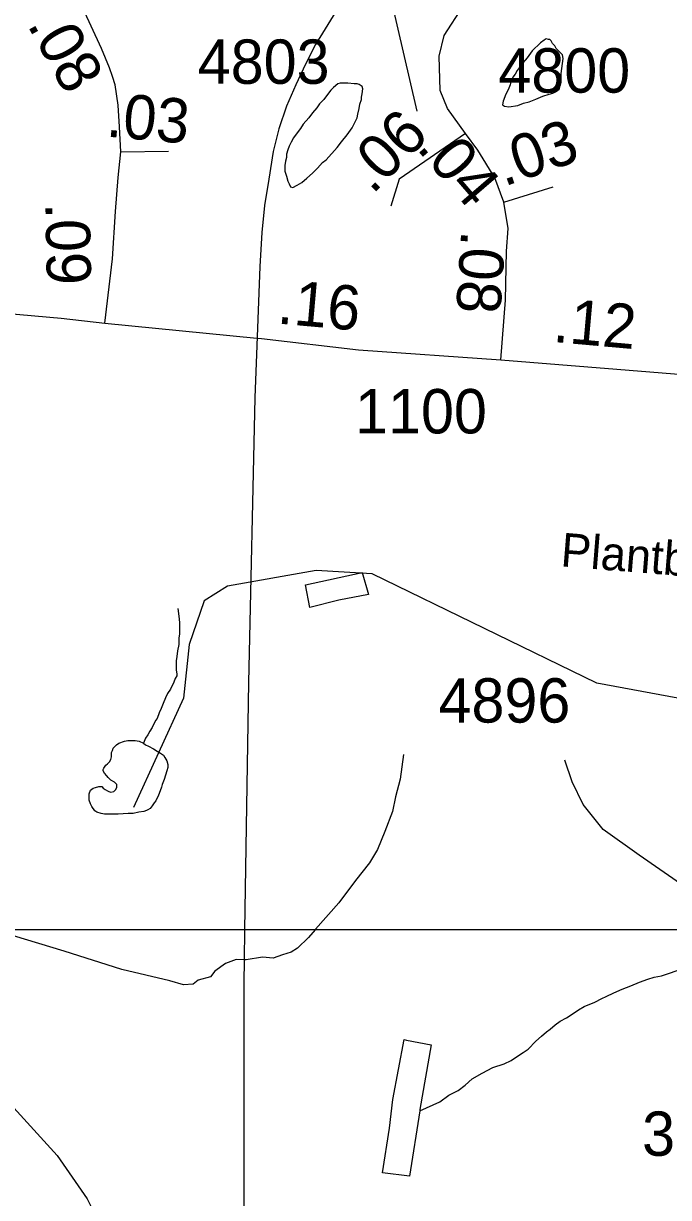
# Model space of a CAD drawing. Extents: x 2001466 to 2224147, y 644118 to 847247.
# Drawn here: x 2051817 to 2053637, y 657420 to 660729 of the extents above; entities that cross this region are included whole.
import ezdxf

# ---------------------------------------------------------------- set-up
doc = ezdxf.new("R2010")
doc.units = 0
for name, color, linetype in [('Exist Hydrographic Creek Single Shore', 7, 'Continuous'), ('Exist Hydrographic Misc Water Feature', 7, 'Continuous'), ('Exist Railroad Mainline', 7, 'Continuous'), ('Exist Road Non-System Type 51', 7, 'Continuous'), ('Exist Road Non-System Type 51 Label', 7, 'Continuous'), ('Exist Road Secondary Mileage Hundredths English Label', 7, 'Continuous'), ('Exist Road Secondary Type 51 Attributed', 7, 'Continuous'), ('Exist Road Secondary Type 51 Number Label', 7, 'Continuous'), ('Map Preparation Inset Cut Line', 7, 'Continuous')]:
    doc.layers.add(name, color=color, linetype=linetype)

msp = doc.modelspace()

# ---------------------------------------------------------------- linework, layer by layer
at = {"layer": 'Exist Hydrographic Creek Single Shore'}
msp.add_lwpolyline([(2055519, 658531.7), (2055344.1, 658633.7), (2055119.1, 658680.9), (2054777.1, 658655), (2054410.1, 658688.8), (2053435, 658869.3), (2052801, 659177.4), (2052643.1, 659187.2), (2052393.2, 659143), (2052327.1, 659101.7), (2052285.1, 658977.9), (2052269.1, 658827.3), (2052128, 658518.5)], dxfattribs=at)
at = {"layer": 'Exist Hydrographic Misc Water Feature'}
for points in [[(2053252.3, 660651.7), (2053238.4, 660631.6), (2053226.3, 660617.6), (2053216.4, 660603.6), (2053210.3, 660595.6), (2053204.6, 660585.6), (2053198.4, 660577.6), (2053192.5, 660565.6), (2053190.4, 660555.6), (2053184.5, 660541.6), (2053178.5, 660529.6), (2053170.7, 660509.5), (2053168.7, 660499.5), (2053174.6, 660495.6), (2053186.7, 660493.6), (2053212.6, 660497.6), (2053228.5, 660503.6), (2053244.5, 660507.7), (2053262.6, 660515.7), (2053282.5, 660523.8), (2053300.5, 660529.8), (2053310.6, 660531.8), (2053318.6, 660535.8), (2053324.5, 660539.8), (2053328.4, 660543.8), (2053332.5, 660557.9), (2053334.6, 660565.9), (2053334.4, 660587.8), (2053338.5, 660615.8), (2053340.3, 660629.8), (2053338.5, 660639.8), (2053330.3, 660647.8), (2053320.2, 660657.8), (2053316.3, 660665.8), (2053310.2, 660671.8), (2053306.3, 660679.8), (2053302.2, 660683.8), (2053298.3, 660683.8), (2053292.3, 660685.7), (2053286.2, 660681.7), (2053276.3, 660673.7), (2053252.3, 660651.7)], [(2052622.8, 660462.5), (2052606.8, 660444.5), (2052598.8, 660432.5), (2052586.9, 660416.4), (2052578.9, 660406.4), (2052572.8, 660394.4), (2052567, 660382.4), (2052562.9, 660372.4), (2052559.1, 660360.4), (2052559.1, 660350.4), (2052557, 660340.5), (2052554.9, 660328.5), (2052555.2, 660312.5), (2052559.1, 660298.5), (2052563.2, 660284.4), (2052567, 660276.4), (2052571.1, 660268.4), (2052577.1, 660266.4), (2052589.2, 660272.5), (2052603.1, 660280.5), (2052617.1, 660292.6), (2052633.1, 660306.6), (2052647, 660320.6), (2052661, 660336.6), (2052671, 660344.7), (2052702.8, 660378.7), (2052714.9, 660394.7), (2052730.9, 660414.8), (2052744.8, 660434.8), (2052758.8, 660462.8), (2052760.8, 660472.8), (2052764.7, 660488.8), (2052766.8, 660500.8), (2052770.7, 660514.7), (2052770.7, 660520.7), (2052772.7, 660530.7), (2052774.6, 660544.8), (2052772.7, 660550.8), (2052764.7, 660556.8), (2052758.6, 660558.8), (2052750.6, 660558.8), (2052732.7, 660560.7), (2052714.7, 660560.7), (2052710.6, 660560.7), (2052704.6, 660558.6), (2052692.5, 660548.6), (2052684.5, 660540.6), (2052674.7, 660528.6), (2052664.7, 660514.6), (2052652.8, 660502.5), (2052644.8, 660490.5), (2052632.7, 660476.6), (2052622.8, 660462.5)], [(2052707.3, 659103), (2052625.3, 659082.8), (2052613.2, 659146.7), (2052773.1, 659181.1), (2052791.2, 659119.1), (2052707.3, 659103)], [(2052253.3, 659080), (2052255.4, 659058.1), (2052257.4, 659040.1), (2052257.4, 659024.1), (2052257.4, 659008.1), (2052255.6, 658996.1), (2052255.6, 658978.1), (2052251.7, 658960.1), (2052249.6, 658944.1), (2052247.8, 658932.1), (2052247.8, 658916.1), (2052247.8, 658906.1), (2052249.6, 658896.1), (2052249.6, 658890.1), (2052245.7, 658882.1), (2052241.8, 658872.1), (2052231.8, 658852.1), (2052223.8, 658840.1), (2052217.8, 658828), (2052211.9, 658812), (2052206, 658798), (2052200, 658786.1), (2052194.1, 658770.1), (2052190, 658764.1), (2052180.1, 658744), (2052174.2, 658734), (2052168, 658724), (2052162.1, 658714), (2052156.1, 658700)], [(2052156.1, 658700), (2052162.1, 658696), (2052170.1, 658692), (2052184, 658684), (2052194.1, 658678), (2052204.1, 658672), (2052212.3, 658666.1), (2052216.2, 658660.1), (2052222.2, 658650.1), (2052224.2, 658640.1), (2052224.2, 658632.1), (2052222.2, 658622.1), (2052218.3, 658610.1), (2052214.4, 658598.1), (2052208.4, 658584.1), (2052206.4, 658576.1), (2052200.4, 658558.1), (2052198.4, 658554), (2052190.4, 658538), (2052186.5, 658532), (2052180.5, 658524), (2052174.4, 658516.1), (2052168.4, 658512.1), (2052164.5, 658510.1), (2052156.5, 658508), (2052142.4, 658506), (2052126.4, 658502), (2052112.4, 658502), (2052084.4, 658499.9), (2052074.5, 658499.9), (2052062.4, 658499.9), (2052054.4, 658499.8), (2052046.4, 658499.8), (2052036.4, 658501.8), (2052024.5, 658505.7), (2052018.5, 658509.7), (2052010.5, 658521.7), (2052006.4, 658529.7), (2052002.5, 658539.7), (2052002.5, 658547.7), (2052002.5, 658557.7), (2052006.2, 658567.7), (2052014.2, 658573.7), (2052020.4, 658575.7), (2052030.4, 658577.7), (2052038.4, 658577.8), (2052042.3, 658573.8), (2052048.3, 658569.8), (2052054.4, 658565.8), (2052058.3, 658563.8), (2052064.3, 658561.8), (2052072.3, 658563.9), (2052078.4, 658569.9), (2052080.3, 658575.9), (2052080.3, 658583.9), (2052074.3, 658589.9), (2052064.3, 658595.8), (2052060.4, 658599.8), (2052056.3, 658603.8), (2052052.4, 658607.8), (2052046.4, 658615.8), (2052042.3, 658621.8), (2052042.1, 658625.8), (2052044.2, 658629.8), (2052050.1, 658637.8), (2052054.2, 658641.8), (2052060.2, 658647.8), (2052064.3, 658653.8), (2052066.1, 658661.8), (2052066.1, 658667.8), (2052066.1, 658673.8), (2052068.2, 658679.8), (2052070.2, 658685.8), (2052074.1, 658689.8), (2052080, 658695.9), (2052086, 658699.9), (2052102, 658705.9), (2052112, 658707.9), (2052124.1, 658707.9), (2052132.1, 658707.9), (2052144, 658705.9), (2052156.1, 658700)], [(2052935.7, 657663.6), (2052991.7, 657689.8), (2053017.8, 657707.8), (2053043.6, 657721.8), (2053063.7, 657735.9), (2053083.6, 657753.9), (2053111.7, 657770), (2053141.6, 657786), (2053173.6, 657796.1), (2053193.5, 657806.1), (2053211.5, 657818.2), (2053227.5, 657828.2), (2053241.5, 657838.2), (2053263.4, 657860.2), (2053279.4, 657874.3), (2053293.3, 657886.3), (2053303.4, 657894.3), (2053317.3, 657906.3), (2053331.3, 657916.3), (2053349.3, 657926.4), (2053365.3, 657936.4), (2053383.2, 657948.5), (2053399.1, 657958.5), (2053429.1, 657970.5), (2053449.2, 657980.5), (2053461.1, 657986.6), (2053483.2, 657996.6), (2053507, 658006.7), (2053531, 658016.7), (2053555, 658026.7), (2053579, 658034.8), (2053597, 658040.8), (2053617.1, 658044.8), (2053637, 658050.9), (2053688.9, 658069)], [(2052935.7, 657663.6), (2052906.2, 657479.7), (2052830.1, 657489.5), (2052850, 657615.5), (2052859.9, 657695.5), (2052891.4, 657865.5), (2052897.6, 657863.5), (2052967.5, 657849.6), (2052935.7, 657667.6), (2052935.7, 657663.6)]]:
    msp.add_lwpolyline(points, dxfattribs=at)
at = {"layer": 'Exist Railroad Mainline'}
for points in [[(2053611.4, 662084.1), (2053440.7, 661834.6), (2053220.9, 661518.3), (2052979, 661180), (2052763.2, 660857.8), (2052703.2, 660769.8), (2052641.4, 660669.7), (2052613.4, 660613.6), (2052585.5, 660555.6), (2052559.4, 660495.5), (2052537.5, 660431.6), (2052521.6, 660367.5), (2052509.6, 660289.5), (2052497.7, 660215.4), (2052489.8, 660139.3), (2052483.8, 660043.5), (2052475.4, 659820.7)], [(2052475.4, 659820.7), (2052469.9, 659673.3), (2052452.4, 658871.1), (2052441.3, 658173.9), (2052440, 658089.7), (2052438.9, 658024.8), (2052439.4, 657252.5), (2052437, 656907.5)]]:
    msp.add_lwpolyline(points, dxfattribs=at)
at = {"layer": 'Exist Road Non-System Type 51'}
for points in [[(2052889.6, 658668.6), (2052880.2, 658598.8), (2052867.2, 658549.1), (2052858.4, 658507.2), (2052837.2, 658451.7), (2052816.2, 658400.1), (2052793.4, 658362.6), (2052754.4, 658313.3), (2052707.1, 658250.3), (2052641.6, 658175.6), (2052640.1, 658173.9)], [(2052440, 658089.7), (2052417.9, 658090.2), (2052387.6, 658078.8), (2052357.2, 658057.4), (2052344.9, 658041.7), (2052310.7, 658032.4), (2052296.4, 658020.6), (2052268.4, 658019.2), (2052230.6, 658030), (2052095.3, 658062.7), (2051932.3, 658114), (2051789.2, 658156.9), (2051737.3, 658173.9)], [(2052640.1, 658173.9), (2052621.1, 658152.1), (2052590.5, 658122.7), (2052572.3, 658111), (2052548.1, 658103.5), (2052521.9, 658094.1), (2052492, 658096.7), (2052445.9, 658089.6), (2052440, 658089.7)]]:
    msp.add_lwpolyline(points, dxfattribs=at)
at = {"layer": 'Exist Road Secondary Type 51 Attributed'}
msp.add_line((2052092.2, 660367.1), (2052226.6, 660368.7), dxfattribs=at)
for points in [[(2053064.6, 660418.6), (2053013.4, 660489.4), (2052993.4, 660540.1), (2052990.2, 660636.2), (2053003.9, 660694.3), (2053057.8, 660777.8), (2053281, 661095.7), (2053384.5, 661239.4)], [(2052092.2, 660367.1), (2052088.4, 660437.1), (2052084.1, 660498.6), (2052075.6, 660555.8), (2052069, 660579.2), (2052059.9, 660603.7), (2052037.4, 660657.6), (2051984.4, 660771.8)], [(2053064.6, 660418.6), (2052877.8, 660289.8), (2052853.5, 660213.7)], [(2053172.3, 660225.3), (2053147, 660294), (2053099.5, 660371.1), (2053064.6, 660418.6)], [(2052047.2, 659884.4), (2052068.5, 660065.1), (2052076.7, 660198.8), (2052084.9, 660294.3), (2052092.2, 660367.1)], [(2053172.3, 660225.3), (2053311.6, 660268.6)], [(2053164.4, 659780.6), (2053177.1, 659948.6), (2053180.2, 660087), (2053185, 660150.3), (2053172.3, 660225.3)], [(2050076.9, 659300), (2050164.5, 659309.5), (2050244.7, 659335.9), (2050317.6, 659374), (2050468.5, 659481.7), (2050697, 659664.4), (2050909.2, 659829.2), (2050995.8, 659889.4), (2051063.8, 659928.5), (2051133.5, 659949.6), (2051234.8, 659954.9), (2051446, 659949.6), (2051614.8, 659925.3), (2051923.6, 659897.9), (2052047.2, 659884.4)], [(2052047.2, 659884.4), (2052476.2, 659842)], [(2052476.2, 659842), (2052489.4, 659840.8), (2052762.8, 659809.1), (2053164.4, 659780.6)], [(2053164.4, 659780.6), (2053491.6, 659754.2), (2053782.4, 659731)], [(2050076.9, 659300), (2050146.6, 659252.5), (2050322.8, 659152.1), (2050571.4, 659004.3), (2050760.4, 658860.6), (2050918.2, 658714.8), (2051097.6, 658522.6), (2051222.2, 658372.6), (2051469.7, 658020.8), (2051619.6, 657858.2), (2051912.5, 657538.1), (2051997, 657415.6), (2052073.5, 657263.5), (2052123.1, 657140.9), (2052158.1, 657015.1)], [(2054293.5, 657880.2), (2054158.6, 658041), (2054145.3, 658057.9), (2054101.7, 658090.6), (2054078.1, 658106.4), (2054035.8, 658129.1), (2053943.6, 658166.8), (2053859.2, 658198.2), (2053763.8, 658247.8), (2053683.5, 658295.8), (2053554.3, 658384.2), (2053452.9, 658456.7), (2053396.1, 658527.7), (2053365.5, 658591.5), (2053345, 658652.5)]]:
    msp.add_lwpolyline(points, dxfattribs=at)
at = {"layer": 'Exist Road Secondary Type 51 Number Label'}
msp.add_line((2052928.2, 660481.4), (2052728.2, 661346.5), dxfattribs=at)
at = {"layer": 'Map Preparation Inset Cut Line'}
for p, q in [((2052441.3, 658173.9), (2051737.3, 658173.9)), ((2052640.1, 658173.9), (2052441.3, 658173.9)), ((2055983.4, 658173.9), (2052640.1, 658173.9))]:
    msp.add_line(p, q, dxfattribs=at)

# ---------------------------------------------------------------- texts
at = {"layer": 'Exist Road Non-System Type 51 Label'}
msp.add_text('Plantbed Ct.', height=95, rotation=355.4566, dxfattribs=at).set_placement((2053331, 659198.8))
at = {"layer": 'Exist Road Secondary Mileage Hundredths English Label'}
for s, rotation, p in [('.08', 298.9731, (2051826.5, 660725.5)), ('.03', 354.9185, (2052048.5, 660410.1)), ('.06', 45.137, (2052801.4, 660244.7)), ('.03', 19.2112, (2053173, 660268.3)), ('.04', 310.7491, (2052924, 660376.5)), ('.09', 271.1167, (2051879, 660222.8)), ('.08', 266.2977, (2053052.8, 660147)), ('.16', 354.9185, (2052531, 659883.2)), ('.12', 354.9185, (2053308.9, 659831.3))]:
    msp.add_text(s, height=125, rotation=rotation, dxfattribs=at).set_placement(p)
at = {"layer": 'Exist Road Secondary Type 51 Number Label'}
for s, p in [('4803', (2052309.1, 660558.5)), ('4800', (2053157.3, 660533.7)), ('1100', (2052753, 659573.2)), ('4896', (2052988.4, 658758.2)), ('3874', (2053562.8, 657537.2))]:
    msp.add_text(s, height=125, dxfattribs=at).set_placement(p)

doc.saveas('drawing.dxf')
